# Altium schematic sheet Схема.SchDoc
size A0; SheetNumber: 0; SheetTotal: 0
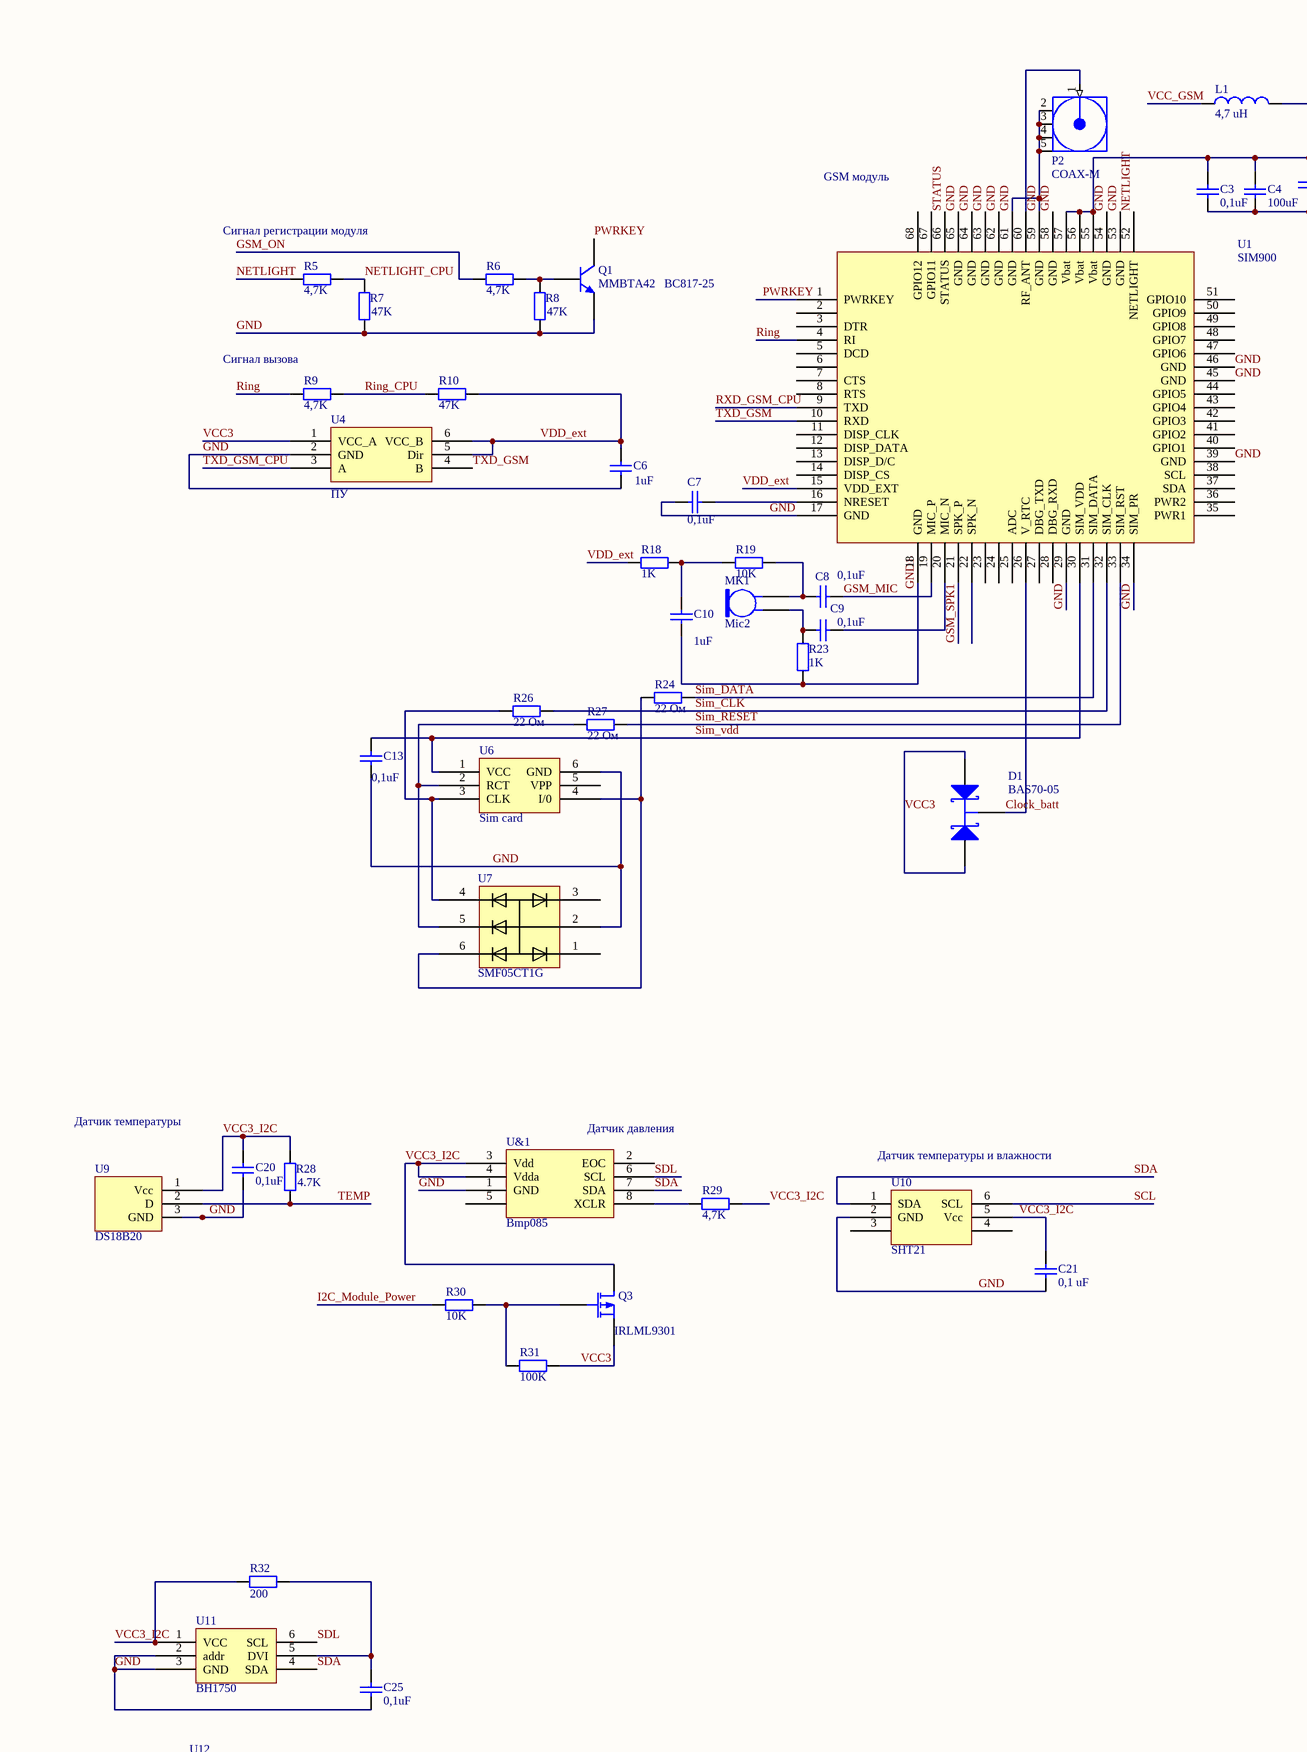
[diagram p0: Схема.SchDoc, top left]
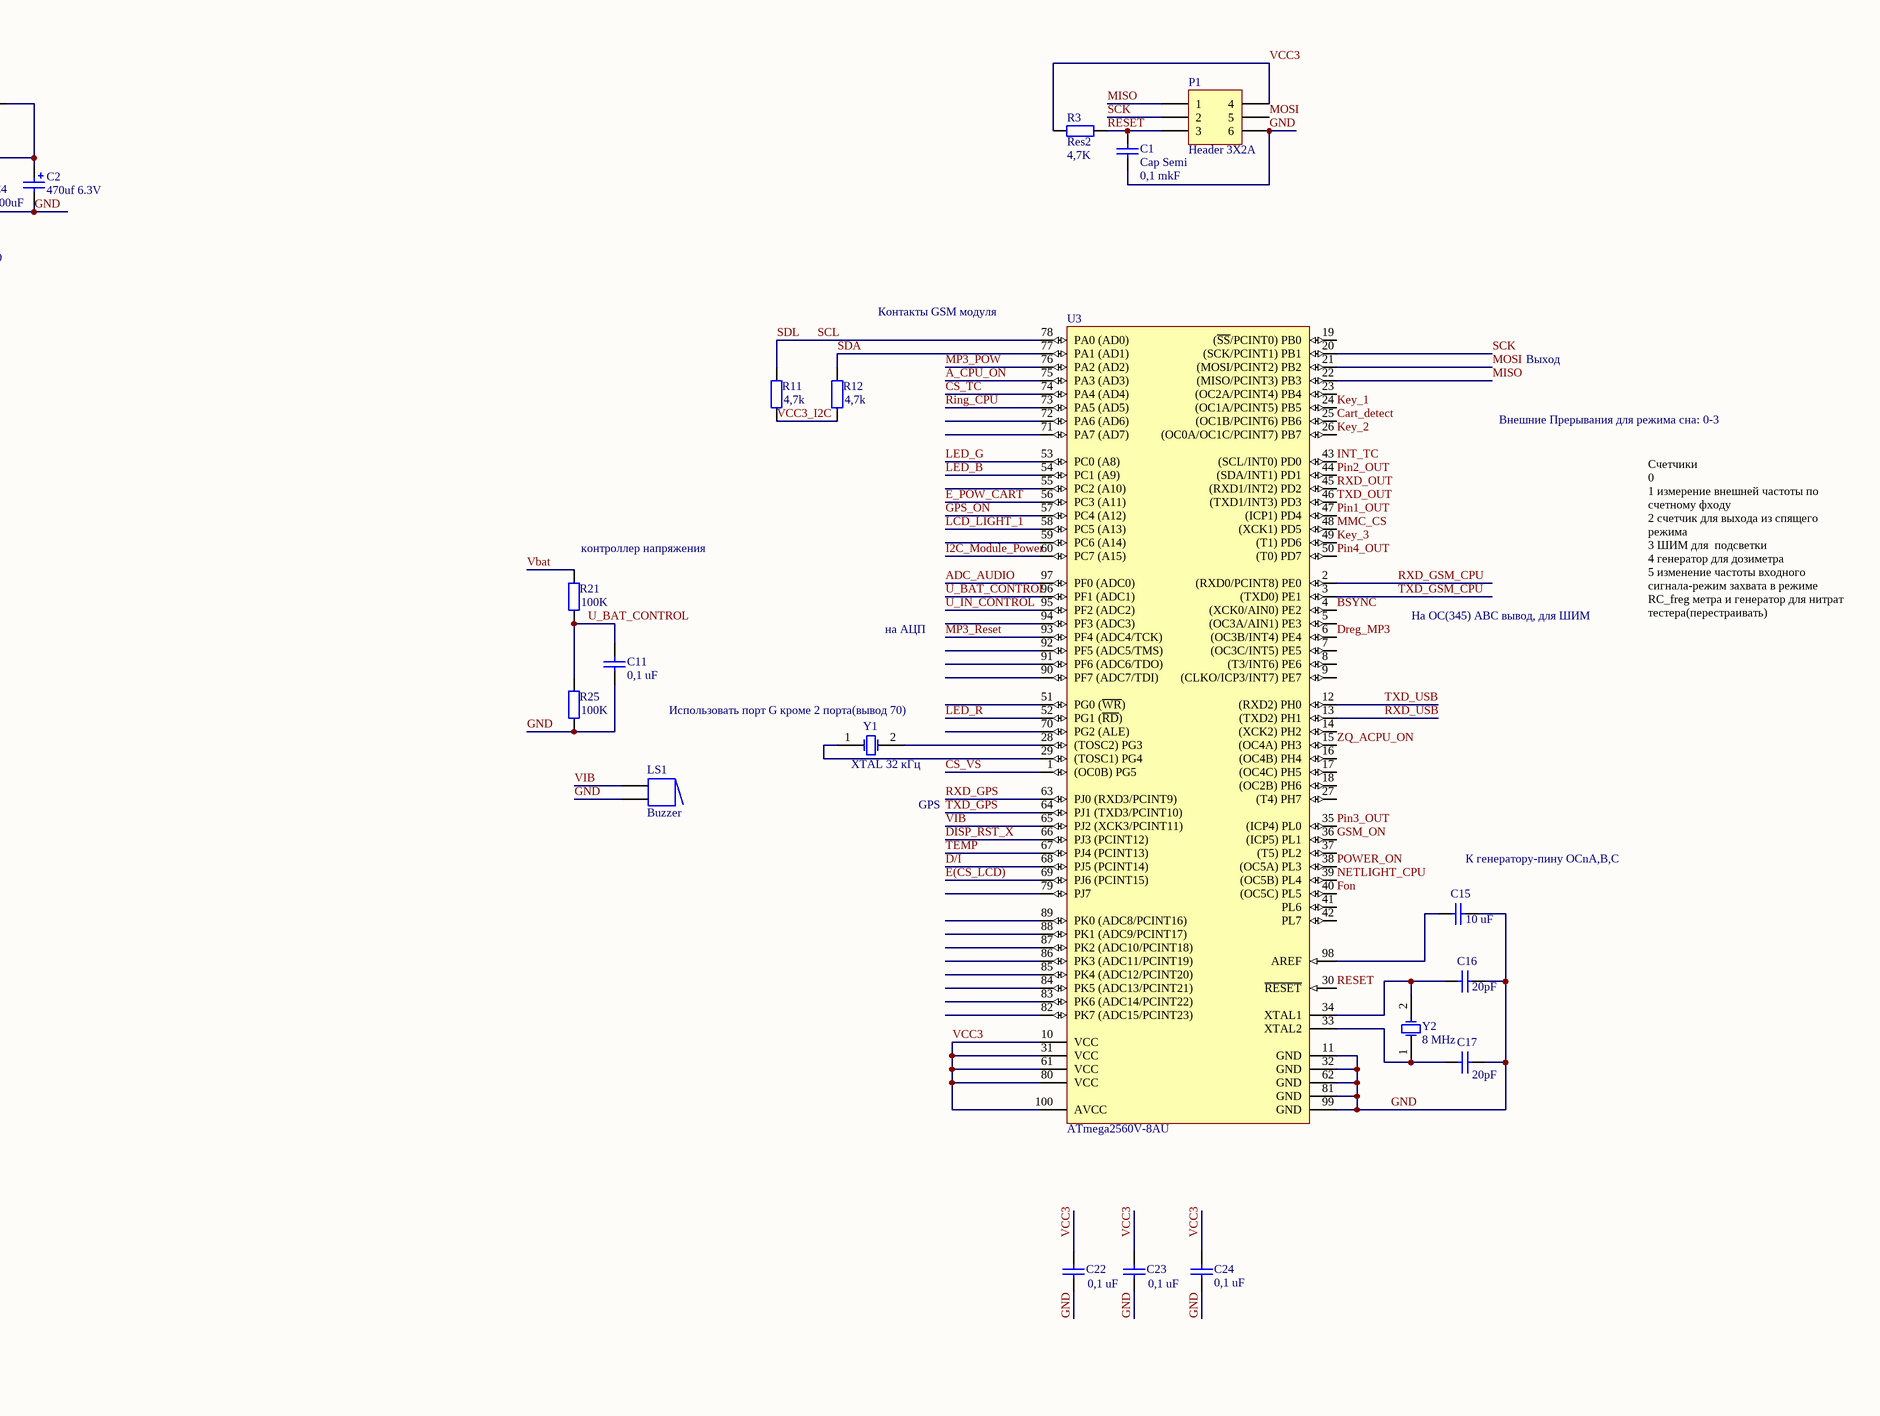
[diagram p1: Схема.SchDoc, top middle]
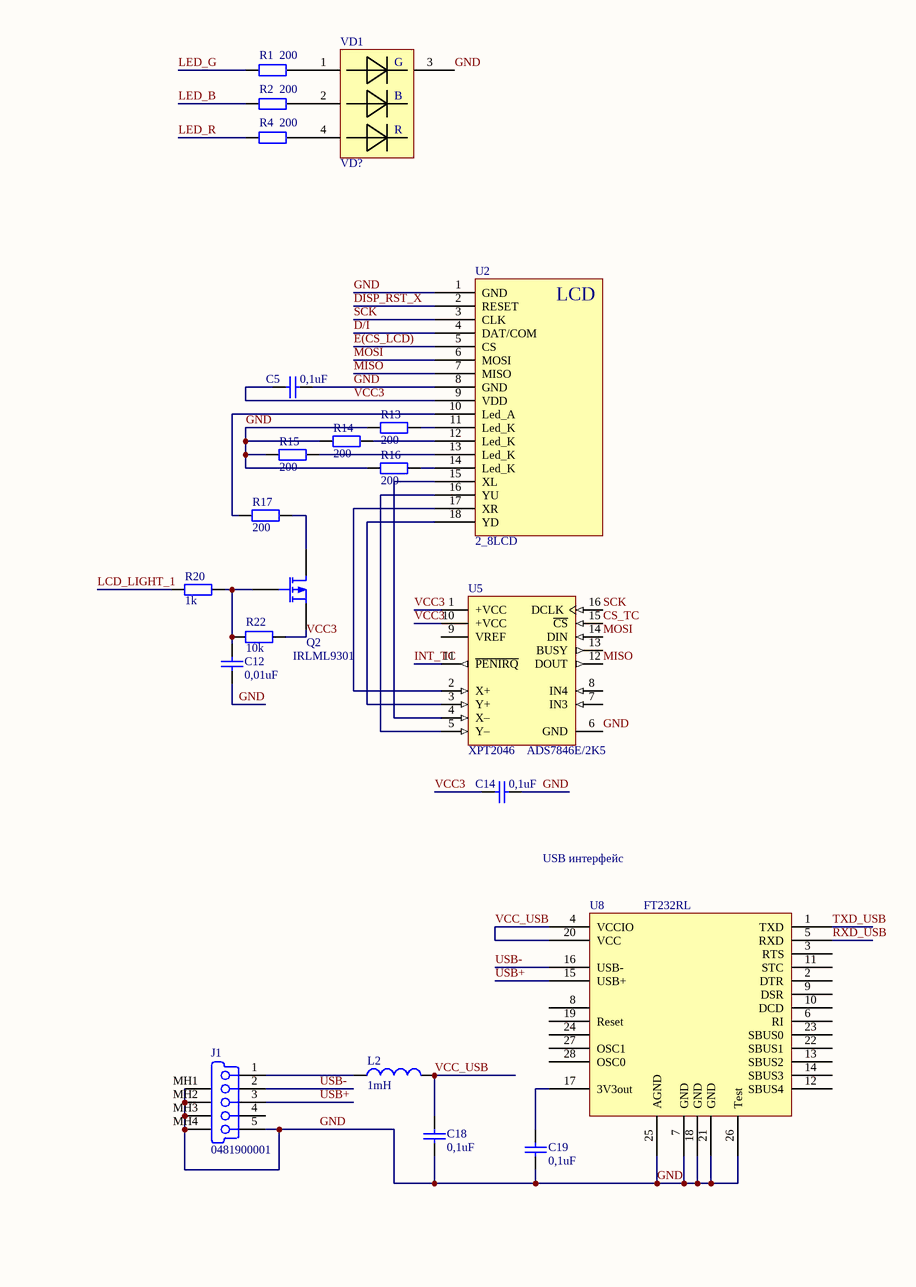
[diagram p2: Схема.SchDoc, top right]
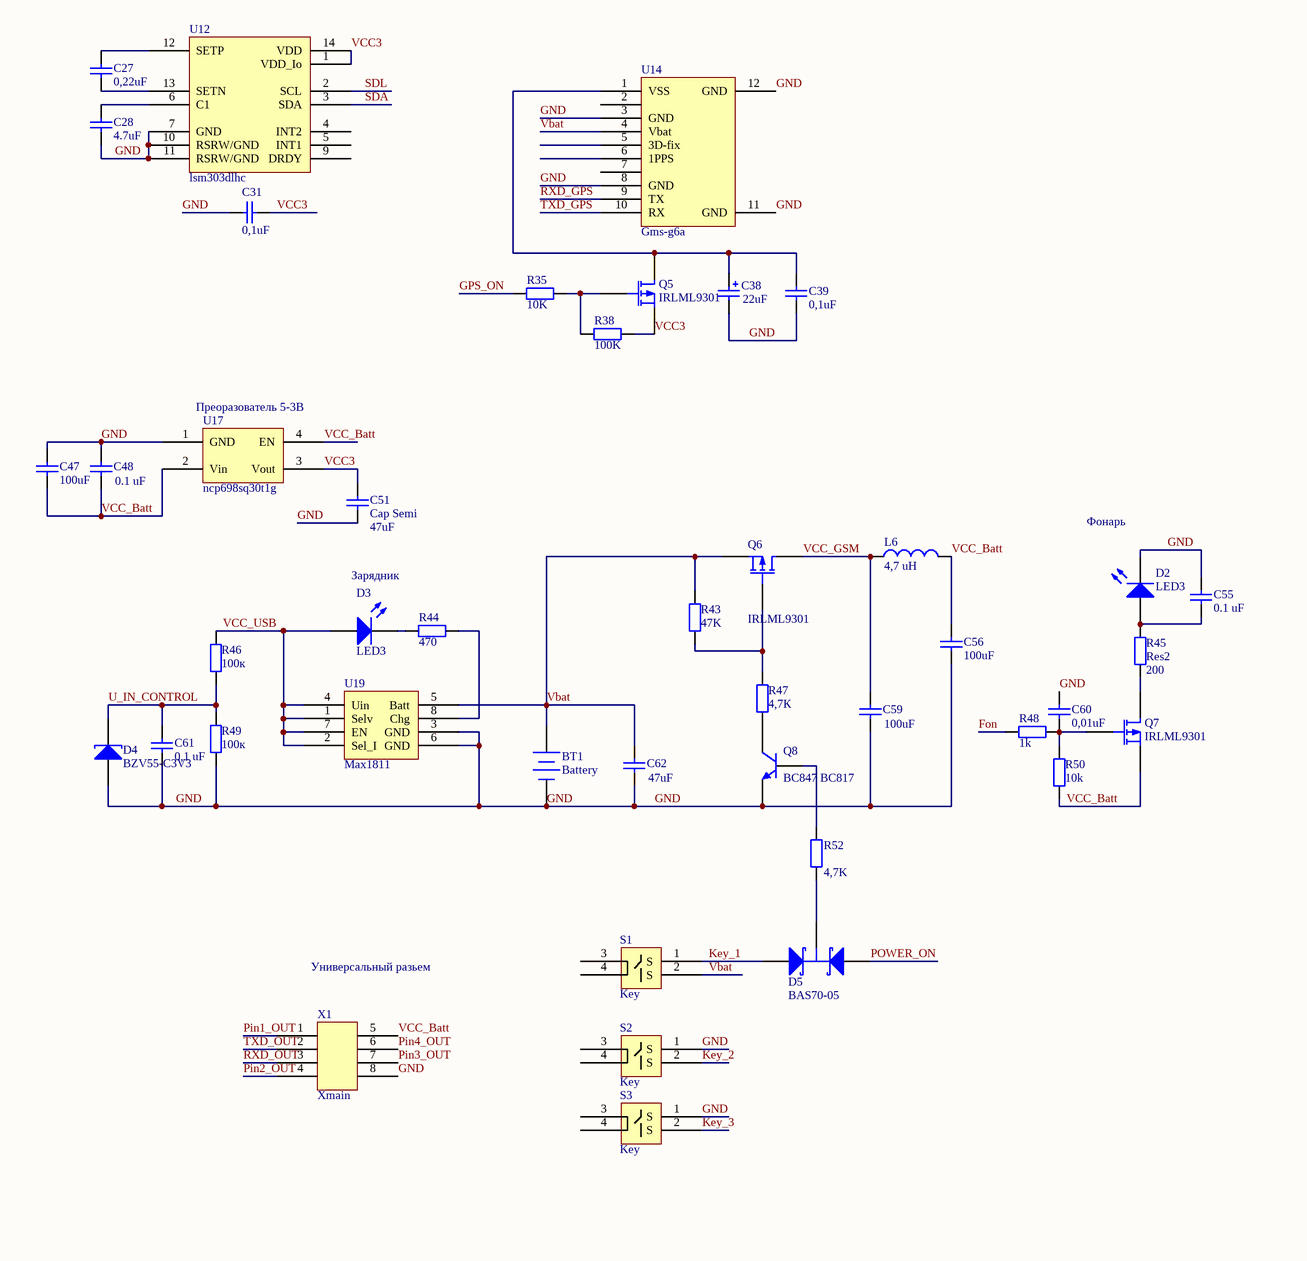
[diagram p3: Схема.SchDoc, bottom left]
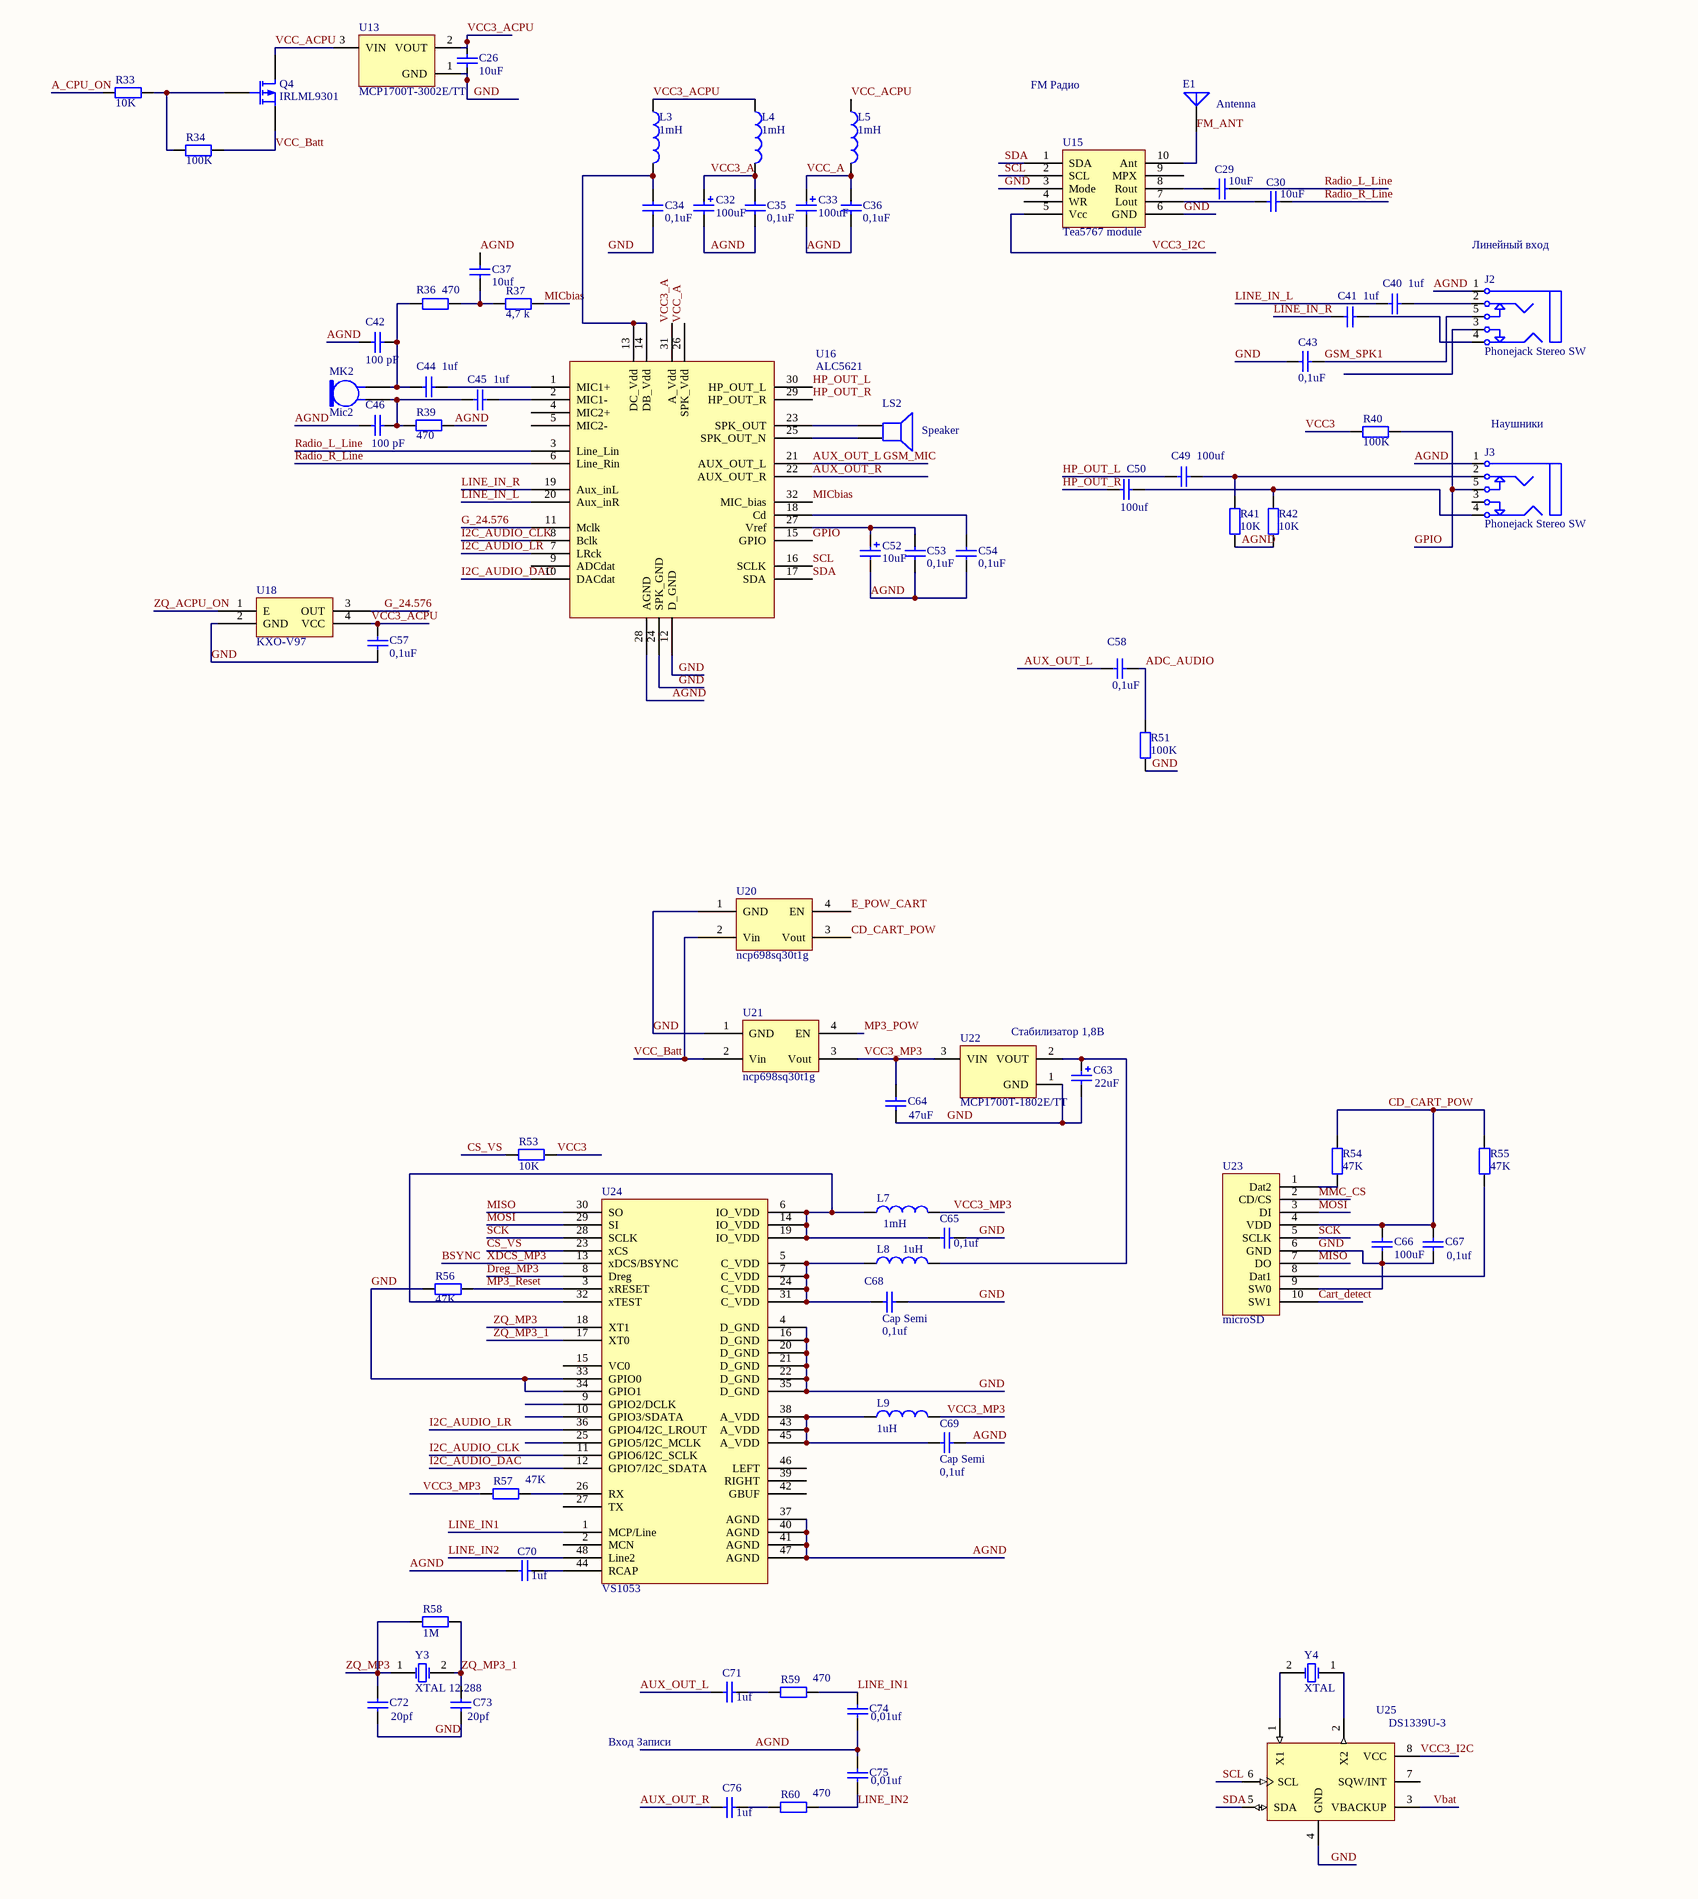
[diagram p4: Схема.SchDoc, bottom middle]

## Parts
BT1  Battery  [BAT-2]
C1  Cap Semi  value 0,1 mkF  [6-0805_L]
C2  value 470uf 6.3V  [HDR1X2]  (hidden comment: Cap Pol2)
C3  value 0,1uF  [C0805]  (hidden comment: Cap Semi)
C4  value 100uF  [C1206]  (hidden comment: Cap Semi)
C5  value 0,1uF  [C0805]  (hidden comment: Cap Semi)
C6  value 1uF  [C0805]  (hidden comment: Cap Semi)
C7  value 0,1uF  [C0805]  (hidden comment: Cap Semi)
C8  value 0,1uF  [C0805]  (hidden comment: Cap Semi)
C9  value 0,1uF  [C0805]  (hidden comment: Cap Semi)
C10  value 1uF  [C0805]  (hidden comment: Cap Semi)
C11  value 0,1 uF  [C0805]  (hidden comment: Cap Semi)
C12  value 0,01uF  [C0805]  (hidden comment: Cap Semi)
C13  value 0,1uF  [C0805]  (hidden comment: Cap Semi)
C14  value 0,1uF  [C0805]  (hidden comment: Cap Semi)
C15  value 10 uF  [C0805]  (hidden comment: Cap Semi)
C16  value 20pF  [C0805]  (hidden comment: Cap Semi)
C17  value 20pF  [C0805]  (hidden comment: Cap Semi)
C18  value 0,1uF  [C0805]  (hidden comment: Cap Semi)
C19  value 0,1uF  [C0805]  (hidden comment: Cap Semi)
C20  value 0,1uF  [C0805]  (hidden comment: Cap Semi)
C21  value 0,1 uF  [C0805]  (hidden comment: Cap Semi)
C22  value 0,1 uF  [C0805]  (hidden comment: Cap Semi)
C23  value 0,1 uF  [C0805]  (hidden comment: Cap Semi)
C24  value 0,1 uF  [C0805]  (hidden comment: Cap Semi)
C25  value 0,1uF  [C0805]  (hidden comment: Cap Semi)
C26  value 10uF  [C0805]  (hidden comment: Cap Semi)
C27  value 0,22uF  [C0805]  (hidden comment: Cap Semi)
C28  value 4.7uF  [C0805]  (hidden comment: Cap Semi)
C29  value 10uF  [C0805]  (hidden comment: Cap Semi)
C30  value 10uF  [C0805]  (hidden comment: Cap Semi)
C31  value 0,1uF  [C0805]  (hidden comment: Cap Semi)
C32  value 100uF  [C1206]  (hidden comment: Cap Pol2)
C33  value 100uF  [C1206]  (hidden comment: Cap Pol2)
C34  value 0,1uF  [C0805]  (hidden comment: Cap Semi)
C35  value 0,1uF  [C0805]  (hidden comment: Cap Semi)
C36  value 0,1uF  [C0805]  (hidden comment: Cap Semi)
C37  value 10uf  [C0805]  (hidden comment: Cap Semi)
C38  value 22uF  [C1206]  (hidden comment: Cap Pol2)
C39  value 0,1uF  [C0805]  (hidden comment: Cap Semi)
C40  value 1uf  [C0805]  (hidden comment: Cap Semi)
C41  value 1uf  [C0805]  (hidden comment: Cap Semi)
C42  value 100 pF  [C0805]  (hidden comment: Cap Semi)
C43  value 0,1uF  [C0805]  (hidden comment: Cap Semi)
C44  value 1uf  [C0805]  (hidden comment: Cap Semi)
C45  value 1uf  [C0805]  (hidden comment: Cap Semi)
C46  value 100 pF  [C0805]  (hidden comment: Cap Semi)
C47  value 100uF  [C1206]  (hidden comment: Cap Semi)
C48  value 0.1 uF  [C0805]  (hidden comment: Cap Semi)
C49  value 100uf  [C1206]  (hidden comment: Cap Semi)
C50  value 100uf  [C1206]  (hidden comment: Cap Semi)
C51  Cap Semi  value 47uF  [C1206]
C52  value 10uF  [C1206]  (hidden comment: Cap Pol2)
C53  value 0,1uF  [C0805]  (hidden comment: Cap Semi)
C54  value 0,1uF  [C0805]  (hidden comment: Cap Semi)
C55  value 0.1 uF  [C0805]  (hidden comment: Cap Semi)
C56  value 100uF  [C1206]  (hidden comment: Cap Semi)
C57  value 0,1uF  [C0805]  (hidden comment: Cap Semi)
C58  value 0,1uF  [C0805]  (hidden comment: Cap Semi)
C59  value 100uF  [C1206]  (hidden comment: Cap Semi)
C60  value 0,01uF  [C0805]  (hidden comment: Cap Semi)
C61  value 0,1 uF  [C0805]  (hidden comment: Cap Semi)
C62  value 47uF  [C1206]  (hidden comment: Cap Semi)
C63  value 22uF  [C0805]  (hidden comment: Cap Pol2)
C64  value 47uF  [C1206]  (hidden comment: Cap Semi)
C65  value 0,1uf  [C0805]  (hidden comment: Cap Semi)
C66  value 100uF  [C1206]  (hidden comment: Cap Semi)
C67  value 0,1uf  [C0805]  (hidden comment: Cap Semi)
C68  Cap Semi  value 0,1uf  [C0805]
C69  Cap Semi  value 0,1uf  [C0805]
C70  value 1uf  [C0805]  (hidden comment: Cap Semi)
C71  value 1uf  [C0805]  (hidden comment: Cap Semi)
C72  value 20pf  [C0805]  (hidden comment: Cap Semi)
C73  value 20pf  [C0805]  (hidden comment: Cap Semi)
C74  value 0,01uf  [C0805]  (hidden comment: Cap Semi)
C75  value 0,01uf  [C0805]  (hidden comment: Cap Semi)
C76  value 1uf  [C0805]  (hidden comment: Cap Semi)
D1  BAS70-05  [SOT-23]
D2  LED3  [BAT-2]
D3  LED3  [BAT-2]
D4  BZV55-C3V3  [3.2X1.6X1.1]
D5  BAS70-05  [SOT-23]
E1  Antenna  [PIN1]
J1  0481900001  [ATB3225]
J2  Phonejack Stereo SW  [AUDIO 3.5]
J3  Phonejack Stereo SW  [AUDIO 3.5]
L1  value 4,7 uH  [C1206]  (hidden comment: Inductor)
L2  value 1mH  [C0805]  (hidden comment: Inductor)
L3  value 1mH  [C1206]  (hidden comment: Inductor)
L4  value 1mH  [C1206]  (hidden comment: Inductor)
L5  value 1mH  [C1206]  (hidden comment: Inductor)
L6  value 4,7 uH  [C1206]  (hidden comment: Inductor)
L7  value 1mH  [C0805]  (hidden comment: Inductor)
L8  value 1uH  [C0805]  (hidden comment: Inductor)
L9  value 1uH  [C0805]  (hidden comment: Inductor)
LS1  Buzzer  [BAT-2]
LS2  Speaker  [PIN2]
MK1  Mic2  [PIN2]
MK2  Mic2  [PIN2]
P1  Header 3X2A  [HDR2X3_CEN]
P2  COAX-M  [sma]
Q1  MMBTA42   BC817-25  [SOT23_N]
Q2  IRLML9301  [VT]
Q3  IRLML9301  [VT]
Q4  IRLML9301  [VT]
Q5  IRLML9301  [VT]
Q6  IRLML9301  [VT]
Q7  IRLML9301  [VT]
Q8  BC847 BC817  [SOT23_N]
R1  value 200  [6-0805_L]  (hidden comment: Res2)
R2  value 200  [6-0805_L]  (hidden comment: Res2)
R3  Res2  value 4,7K  [6-0805_L]
R4  value 200  [6-0805_L]  (hidden comment: Res2)
R5  value 4,7K  [C0805]  (hidden comment: Res2)
R6  value 4,7K  [C0805]  (hidden comment: Res2)
R7  value 47K  [C0805]  (hidden comment: Res2)
R8  value 47K  [C0805]  (hidden comment: Res2)
R9  value 4,7K  [C0805]  (hidden comment: Res2)
R10  value 47K  [C0805]  (hidden comment: Res2)
R11  value 4,7k  [6-0805_L]  (hidden comment: Res2)
R12  value 4,7k  [6-0805_L]  (hidden comment: Res2)
R13  value 200  [6-0805_L]  (hidden comment: Res2)
R14  value 200  [6-0805_L]  (hidden comment: Res2)
R15  value 200  [6-0805_L]  (hidden comment: Res2)
R16  value 200  [6-0805_L]  (hidden comment: Res2)
R17  value 200  [6-0805_L]  (hidden comment: Res2)
R18  value 1K  [C0805]  (hidden comment: Res2)
R19  value 10K  [C0805]  (hidden comment: Res2)
R20  value 1k  [6-0805_L]  (hidden comment: Res2)
R21  value 100K  [C0805]  (hidden comment: Res2)
R22  value 10k  [6-0805_L]  (hidden comment: Res2)
R23  value 1K  [C0805]  (hidden comment: Res2)
R24  value 22 Ом  [C0805]  (hidden comment: Res2)
R25  value 100K  [6-0805_L]  (hidden comment: Res2)
R26  value 22 Ом  [C0805]  (hidden comment: Res2)
R27  value 22 Ом  [C0805]  (hidden comment: Res2)
R28  value 4.7K  [6-0805_L]  (hidden comment: Res2)
R29  value 4,7K  [6-0805_L]  (hidden comment: Res2)
R30  value 10K  [6-0805_N]  (hidden comment: Res2)
R31  value 100K  [6-0805_N]  (hidden comment: Res2)
R32  value 200  [6-0805_L]  (hidden comment: Res2)
R33  value 10K  [6-0805_N]  (hidden comment: Res2)
R34  value 100K  [6-0805_N]  (hidden comment: Res2)
R35  value 10K  [6-0805_N]  (hidden comment: Res2)
R36  value 470  [C0805]  (hidden comment: Res2)
R37  value 4,7 k  [C0805]  (hidden comment: Res2)
R38  value 100K  [6-0805_N]  (hidden comment: Res2)
R39  value 470  [C0805]  (hidden comment: Res2)
R40  value 100K  [6-0805_N]  (hidden comment: Res2)
R41  value 10K  [6-0805_N]  (hidden comment: Res2)
R42  value 10K  [6-0805_N]  (hidden comment: Res2)
R43  value 47K  [6-0805_N]  (hidden comment: Res2)
R44  value 470  [6-0805_L]  (hidden comment: Res2)
R45  Res2  value 200  [6-0805_L]
R46  value 100к  [6-0805_L]  (hidden comment: Res2)
R47  value 4,7К  [6-0805_N]  (hidden comment: Res2)
R48  value 1k  [6-0805_L]  (hidden comment: Res2)
R49  value 100к  [6-0805_L]  (hidden comment: Res2)
R50  value 10k  [6-0805_L]  (hidden comment: Res2)
R51  value 100K  [C0805]  (hidden comment: Res2)
R52  value 4,7K  [6-0805_L]  (hidden comment: Res2)
R53  value 10K  [C0805]  (hidden comment: Res2)
R54  value 47K  [C0805]  (hidden comment: Res2)
R55  value 47K  [C0805]  (hidden comment: Res2)
R56  value 47K  [C0805]  (hidden comment: Res2)
R57  value 47K  [C0805]  (hidden comment: Res2)
R58  value 1M  [C0805]  (hidden comment: Res2)
R59  value 470  [C0805]  (hidden comment: Res2)
R60  value 470  [C0805]  (hidden comment: Res2)
S1  Key  [Key]
S2  Key  [Key]
S3  Key  [Key]
U1  SIM900  [SIM900_]
U2  2_8LCD  [LCD 2.8]
U3  ATmega2560V-8AU  [100]
U4  ПУ  [Преобразователь уровней SN74LVC1T45]
U5  XPT2046    ADS7846E/2K5  [TC]
U6  Sim card  [SIM-06]
U7  SMF05CT1G  [SMF05CT1G]
U8  FT232RL  [FT232RL]
U9  DS18B20  [DS18B20]
U10  SHT21  [Датчик]
U11  BH1750  [BH1750]
U12  lsm303dlhc  [lsm303dlhc]
U13  MCP1700T-3002E/TT  [VT]
U14  Gms-g6a  [GPS Gms-g6a]
U15  Tea5767 module  [FM AR1310]
U16  ALC5621  [AUDIO CODEC]
U17  ncp698sq30t1g  [St_3V0]
U18  KXO-V97  [25]
U19  Max1811  [SOIC8N_N]
U20  ncp698sq30t1g  [St_3V0_ver2]
U21  ncp698sq30t1g  [St_3V0]
U22  MCP1700T-1802E/TT  [VT]
U23  microSD  [microSD_PCB]
U24  VS1053  [DIP8]
U25  DS1339U-3  [8uSOP]
U&1  Bmp085  [Датчик давления Bmp085]
VD1  VD?  [RGB_5mm_Led]
X1  Xmain  [Xmain]
Y1  XTAL 32 кГц  [R38]
Y2  8 MHz  [HC-49U]
Y3  XTAL 12.288  [ZQ]
Y4  XTAL  [32768]

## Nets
A_CPU_ON: R33.2 U3.75(PA3_(AD3))
ADC_AUDIO: C58.2 R51.1 U3.97(PF0_(ADC0))
AGND: C32.2 C33.2 C35.2 C36.2 C37.2 C42.1 C46.1 C52.2 C53.2 C54.2 C69.1 C70.2 C74.2 C75.1 J2.1 J3.1 R39.1 R41.2 R42.2 U16.28(AGND) U24.37(AGND) U24.40(AGND) U24.41(AGND) U24.47(AGND)
AUX_OUT_L: C8.2 C58.1 C71.2 U1.19(MIC_P) U16.21(AUX_OUT_L)  [also labelled GSM_MIC]
AUX_OUT_R: C76.2 U16.22(AUX_OUT_R)
BSYNC: U3.4((XCK0/AIN0)_PE2) U24.13(xDCS/BSYNC)  [also labelled XDCS_MP3]
Cart_detect: U3.25((OC1B/PCINT6)_PB6) U23.10(SW1)
CD_CART_POW: C66.2 C67.1 R54.1 R55.1 U20.3(Vout) U23.4(VDD)
Clock_batt: D1.3(K) U1.26(V_RTC)
CS_TC: U3.74(PA4_(AD4)) U5.15(~{CS})
CS_VS: R53.2 U3.1((OC0B)_PG5) U24.23(xCS)
D/I: U2.4(DAT/COM) U3.68(PJ5_(PCINT14))
DISP_RST_X: U2.2(RESET) U3.66(PJ3_(PCINT12))
Dreg_MP3: U3.6((OC3B/INT4)_PE4) U24.8(Dreg)
E(CS_LCD): U2.5(CS) U3.69(PJ6_(PCINT15))
E_POW_CART: U3.56(PC3_(A11)) U20.4(EN)
FM_ANT: E1.1(A) U15.10(Ant)
Fon: R48.1 U3.40((OC5C)_PL5)
G_24.576: U16.11(Mclk) U18.3(OUT)
GND: BT1.2(-) C1.1 C2.2 C3.2 C4.2 C5.2 C6.1 C7.1 C11.1 C12.2 C13.1 C14.2 C15.1 C16.2 C17.2 C18.1 C19.1 C20.2 C21.1 C22.1 C23.1 C24.1 C25.2 C26.1 C28.1 C31.2 C34.2 C38.2 C39.2 C43.1 C47.1 C48.2 C51.1 C55.1 C56.2 C57.2 C59.2 C60.1 C61.2 C62.2 C63.2 C64.2 C65.1 C66.1 C67.2 C68.1 C72.2 C73.2 D2.2(K) D4.1(A) J1.5(GND) J1.MH1(Tab) J1.MH2(Tab) J1.MH3(Tab) J1.MH4(Tab) LS1.2 P1.6 P2.2(GND) P2.3(GND) P2.4(GND) P2.5(GND) Q1.2(E) Q8.2(E) R7.2 R8.2 R13.1 R14.1 R15.1 R16.1 R25.2 R49.1 R51.2 R56.1 S2.1(S) S3.1(S) U1.17(GND) U1.29(GND) U1.34(SIM_PR) U1.39(GND) U1.45(GND) U1.46(GND) U1.53(GND) U1.54(GND) U1.58(GND) U1.59(GND) U1.61(GND) U1.62(GND) U1.63(GND) U1.64(GND) U1.65(GND) U2.1(GND) U2.8(GND) U3.11(GND) U3.32(GND) U3.62(GND) U3.81(GND) U3.99(GND) U4.2(GND) U5.6(GND) U6.6(GND) U7.2 U8.7(GND) U8.18(GND) U8.21(GND) U8.25(AGND) U8.26(Test) U9.3(GND) U10.2(GND) U11.2(addr) U11.3(GND) U12.7(GND) U12.10(RSRW/GND) U12.11(RSRW/GND) U13.1(GND) U14.3(GND) U14.8(GND) U14.11(GND) U14.12(GND) U15.3(Mode) U15.6(GND) U16.12(D_GND) U16.24(SPK_GND) U17.1(GND) U18.2(GND) U19.3(GND) U19.6(GND) U20.1(GND) U21.1(GND) U22.1(GND) U23.6(GND) U23.9(SW0) U24.4(D_GND) U24.16(D_GND) U24.20(D_GND) U24.21(D_GND) U24.22(D_GND) U24.33(GPIO0) U24.34(GPIO1) U24.35(D_GND) U25.4(GND) U&1.1(GND) VD1.3 X1.8
GND1: C10.1 R23.1 U1.18(GND)
GPIO: J3.5 R40.2 U16.15(GPIO)
GPS_ON: R35.2 U3.57(PC4_(A12))
GSM_ON: R6.1 U3.36((ICP5)_PL1)
GSM_SPK1: C43.2 J2.5 U1.21(SPK_P)
HP_OUT_L: C49.1 U16.30(HP_OUT_L)
HP_OUT_R: C50.1 U16.29(HP_OUT_R)
I2C_AUDIO_CLK: U16.8(Bclk) U24.11(GPIO6/I2C_SCLK)
I2C_AUDIO_DAC: U16.10(DACdat) U24.12(GPIO7/I2C_SDATA)
I2C_AUDIO_LR: U16.7(LRck) U24.36(GPIO4/I2C_LROUT)
I2C_Module_Power: R30.2 U3.60(PC7_(A15))
INT_TC: U3.43((SCL/INT0)_PD0) U5.11(~{PENIRQ})
Key_1: D5.2(A2) S1.1(S) U3.24((OC1A/PCINT5)_PB5)
Key_2: S2.2(S) U3.26((OC0A/OC1C/PCINT7)_PB7)
Key_3: S3.2(S) U3.49((T1)_PD6)
LCD_LIGHT_1: R20.1 U3.58(PC5_(A13))
LED_B: R2.1 U3.54(PC1_(A9))
LED_G: R1.1 U3.53(PC0_(A8))
LED_R: R4.1 U3.52(PG1_(~{RD}))
LINE_IN1: C74.1 R59.2 U24.1(MCP/Line)
LINE_IN2: C75.2 R60.2 U24.48(Line2)
LINE_IN_L: C40.1 U16.20(Aux_inR)
LINE_IN_R: C41.1 U16.19(Aux_inL)
MICbias: R37.1 U16.32(MIC_bias)
MISO: P1.1 U2.7(MISO) U3.22((MISO/PCINT3)_PB3) U5.12(DOUT) U23.7(DO) U24.30(SO)
MMC_CS: U3.48((XCK1)_PD5) U23.2(CD/CS)
MOSI: P1.5 U2.6(MOSI) U3.21((MOSI/PCINT2)_PB2) U5.14(DIN) U23.3(DI) U24.29(SI)
MP3_POW: U3.76(PA2_(AD2)) U21.4(EN)
MP3_Reset: R56.2 U3.93(PF4_(ADC4/TCK)) U24.3(xRESET)
NETLIGHT: R5.1 U1.52(NETLIGHT)
NETLIGHT_CPU: R5.2 R7.1 U3.39((OC5B)_PL4)
Pin1_OUT: U3.47((ICP1)_PD4) X1.1
Pin2_OUT: U3.44((SDA/INT1)_PD1) X1.4
Pin3_OUT: U3.35((ICP4)_PL0) X1.7
Pin4_OUT: U3.50((T0)_PD7) X1.6
POWER_ON: D5.1(A1) U3.38((OC5A)_PL3)
PWRKEY: Q1.3(C) U1.1(PWRKEY)
Radio_L_Line: C29.2 U16.3(Line_Lin)
Radio_R_Line: C30.2 U16.6(Line_Rin)
RESET: C1.2 P1.3 R3.1 U3.30(~{RESET})
Ring: R9.1 U1.4(RI)
Ring_CPU: R9.2 R10.1 U3.73(PA5_(AD5))
RXD_GPS: U3.63(PJ0_(RXD3/PCINT9)) U14.9(TX)
RXD_GSM_CPU: U1.9(TXD) U3.2((RXD0/PCINT8)_PE0)
RXD_OUT: U3.45((RXD1/INT2)_PD2) X1.3
RXD_USB: U3.13((TXD2)_PH1) U8.5(RXD)
SCK: P1.2 U2.3(CLK) U3.20((SCK/PCINT1)_PB1) U5.16(DCLK) U23.5(SCLK) U24.28(SCLK)
SCL: R11.1 U3.78(PA0_(AD0)) U10.6(SCL) U11.6(SCL) U12.2(SCL) U15.2(SCL) U16.16(SCLK) U25.6(SCL) U&1.6(SCL)  [also labelled SDL]
SDA: R12.1 U3.77(PA1_(AD1)) U10.1(SDA) U11.4(SDA) U12.3(SDA) U15.1(SDA) U16.17(SDA) U25.5(SDA) U&1.7(SDA)
Sim_CLK: R26.2 U1.32(SIM_CLK)
Sim_DATA: R24.2 U1.31(SIM_DATA)
Sim_RESET: R27.2 U1.33(SIM_RST)
Sim_vdd: C13.2 U1.30(SIM_VDD) U6.1(VCC)
STATUS: U1.66(STATUS)
TEMP: R28.2 U3.67(PJ4_(PCINT13)) U9.2(D)
TXD_GPS: U3.64(PJ1_(TXD3/PCINT10)) U14.10(RX)
TXD_GSM: U1.10(RXD) U4.4(B)
TXD_GSM_CPU: U3.3((TXD0)_PE1) U4.3(A)
TXD_OUT: U3.46((TXD1/INT3)_PD3) X1.2
TXD_USB: U3.12((RXD2)_PH0) U8.1(TXD)
U_BAT_CONTROL: C11.2 R21.2 R25.1 U3.96(PF1_(ADC1))
U_IN_CONTROL: C61.1 D4.2(K) R46.1 R49.2 U3.95(PF2_(ADC2))
USB+: J1.3(D+) U8.15(USB+)
USB-: J1.2(D-) U8.16(USB-)
Vbat: BT1.1(+) C62.1 Q6.2(S) R21.1 R43.1 S1.2(S) U14.4(Vbat) U19.5(Batt) U25.3(VBACKUP)
VCC3: C5.1 C14.1 C22.2 C23.2 C24.2 C31.1 C51.2 D1.1(A1) D1.2(A2) P1.4 Q2.2(S) Q3.2(S) Q5.2(S) R3.2 R22.2 R31.1 R38.1 R40.1 R53.1 U2.9(VDD) U3.10(VCC) U3.31(VCC) U3.61(VCC) U3.80(VCC) U3.100(AVCC) U4.1(VCC_A) U5.1(+VCC) U5.10(+VCC) U12.1(VDD_Io) U12.14(VDD) U17.3(Vout)
VCC3_A: C32.1 C35.1 L4.2 U16.31(A_Vdd)
VCC3_ACPU: C26.2 C57.1 L3.1 L4.1 U13.2(VOUT) U18.4(VCC)
VCC3_I2C: C20.1 C21.2 Q3.3(D) R11.2 R12.2 R28.1 R29.2 R32.2 U9.1(Vcc) U10.5(Vcc) U11.1(VCC) U15.5(Vcc) U25.8(VCC) U&1.3(Vdd) U&1.4(Vdda)
VCC3_MP3: C64.1 L7.2 L9.2 R57.1 U21.3(Vout) U22.3(VIN)
VCC_A: C33.1 C36.1 L5.2 U16.26(SPK_Vdd)
VCC_ACPU: L5.1 Q4.3(D) U13.3(VIN)
VCC_Batt: C47.2 C48.1 C56.1 L6.2 Q4.2(S) Q7.2(S) R34.1 R50.1 U17.2(Vin) U17.4(EN) U20.2(Vin) U21.2(Vin) X1.5
VCC_GSM: C59.1 L1.1 L6.1 Q6.3(D)
VCC_USB: C18.2 D3.1(A) L2.2 R46.2 U8.4(VCCIO) U8.20(VCC) U19.1(Selv) U19.2(Sel_I) U19.4(Uin) U19.7(EN)
VDD_ext: C6.2 R10.2 R18.2 U1.15(VDD_EXT) U4.5(Dir) U4.6(VCC_B)
VIB: LS1.1 U3.65(PJ2_(XCK3/PCINT11))
ZQ_ACPU_ON: U3.15((OC4A)_PH3) U18.1(E)
ZQ_MP3: C72.1 R58.1 U24.18(XT1) Y3.1(OSC1)
ZQ_MP3_1: C73.1 R58.2 U24.17(XT0) Y3.2(OSC2)
NetC2_1: C2.1 C3.1 C4.1 L1.2 U1.55(Vbat) U1.56(Vbat) U1.57(Vbat)
NetC7_2: C7.2 U1.16(NRESET)
NetC8_1: C8.1 MK1.2 R19.1
NetC9_1: C9.1 MK1.1 R23.2
NetC9_2: C9.2 U1.20(MIC_N)
NetC10_2: C10.2 R18.1 R19.2
NetC12_1: C12.1 Q2.1(G) R20.2 R22.1
NetC15_2: C15.2 U3.98(AREF)
NetC16_1: C16.1 U3.34(XTAL1) Y2.2(OSC2)
NetC17_1: C17.1 U3.33(XTAL2) Y2.1(OSC1)
NetC19_2: C19.2 U8.17(3V3out)
NetC25_1: C25.1 R32.1 U11.5(DVI)
NetC27_1: C27.1 U12.13(SETN)
NetC27_2: C27.2 U12.12(SETP)
NetC28_2: C28.2 U12.6(C1)
NetC29_1: C29.1 U15.8(Rout)
NetC30_1: C30.1 U15.7(Lout)
NetC34_1: C34.1 L3.2 U16.13(DC_Vdd) U16.14(DB_Vdd)
NetC37_1: C37.1 R36.2 R37.2
NetC38_1: C38.1 C39.1 Q5.3(D) U14.1(VSS)
NetC40_2: C40.2 J2.2
NetC41_2: C41.2 J2.4
NetC42_2: C42.2 C44.1 MK2.2 R36.1
NetC44_2: C44.2 U16.1(MIC1+)
NetC45_1: C45.1 C46.2 MK2.1 R39.2
NetC45_2: C45.2 U16.2(MIC1-)
NetC49_2: C49.2 J3.2 R41.1
NetC50_2: C50.2 J3.4 R42.1
NetC52_1: C52.1 C53.1 U16.27(Vref)
NetC54_1: C54.1 U16.18(Cd)
NetC55_2: C55.2 D2.1(A) R45.2
NetC60_2: C60.2 Q7.1(G) R48.2 R50.2
NetC63_1: C63.1 L8.2 U22.2(VOUT)
NetC65_2: C65.2 L7.1 U24.6(IO_VDD) U24.14(IO_VDD) U24.19(IO_VDD) U24.32(xTEST)
NetC68_2: C68.2 L8.1 U24.5(C_VDD) U24.7(C_VDD) U24.24(C_VDD) U24.31(C_VDD)
NetC69_2: C69.2 L9.1 U24.38(A_VDD) U24.43(A_VDD) U24.45(A_VDD)
NetC70_1: C70.1 U24.44(RCAP)
NetC71_1: C71.1 R59.1
NetC76_1: C76.1 R60.1
NetD3_2: D3.2(K) R44.1
NetD5_3: D5.3(K) R52.2
NetJ1_1: J1.1(V_BUS_(5V)) L2.1
NetLS2_1: LS2.1 U16.23(SPK_OUT)
NetLS2_2: LS2.2 U16.25(SPK_OUT_N)
NetP2_1: P2.1(Signal) U1.60(RF_ANT)
NetQ1_1: Q1.1(B) R6.2 R8.1
NetQ2_3: Q2.3(D) R17.2
NetQ3_1: Q3.1(G) R30.1 R31.2
NetQ4_1: Q4.1(G) R33.1 R34.2
NetQ5_1: Q5.1(G) R35.1 R38.2
NetQ6_1: Q6.1(G) R43.2 R47.1
NetQ7_3: Q7.3(D) R45.1
NetQ8_1: Q8.1(B) R52.1
NetQ8_3: Q8.3(C) R47.2
NetR1_2: R1.2 VD1.1
NetR2_2: R2.2 VD1.2
NetR4_2: R4.2 VD1.4
NetR13_2: R13.2 U2.11(Led_K)
NetR14_2: R14.2 U2.12(Led_K)
NetR15_2: R15.2 U2.13(Led_K)
NetR16_2: R16.2 U2.14(Led_K)
NetR17_1: R17.1 U2.10(Led_A)
NetR24_1: R24.1 U6.4(I/0) U7.6
NetR26_1: R26.1 U6.3(CLK) U7.4
NetR27_1: R27.1 U6.2(RCT) U7.5
NetR29_1: R29.1 U&1.8(XCLR)
NetR44_2: R44.2 U19.8(Chg)
NetR54_2: R54.2 U23.1(Dat2)
NetR55_2: R55.2 U23.8(Dat1)
NetR57_2: R57.2 U24.26(RX)
NetU2_15: U2.15(XL) U5.4(X–)
NetU2_16: U2.16(YU) U5.5(Y–)
NetU2_17: U2.17(XR) U5.2(X+)
NetU2_18: U2.18(YD) U5.3(Y+)
NetU3_28: U3.28((TOSC2)_PG3) Y1.2(OSC2)
NetU3_29: U3.29((TOSC1)_PG4) Y1.1(OSC1)
NetU25_1: U25.1(X1) Y4.2(OSC2)
NetU25_2: U25.2(X2) Y4.1(OSC1)

Not connected (* = marked no-connect by the designer): J1 4(NC); J2 3; J3 3; S1 3 4; S2 3 4; S3 3 4; U1 2 3(DTR) 5(DCD) 6 7(CTS) 8(RTS) 11(DISP_CLK) 12(DISP_DATA) 13(DISP_D/C) 14(DISP_CS) 22(SPK_N) 23 24 25(ADC) 27(DBG_TXD) 28(DBG_RXD) 35(PWR1) 36(PWR2) 37(SDA) 38(SCL) 40(GPIO1) 41(GPIO2) 42(GPIO3) 43(GPIO4) 44(GPIO5) 47(GPIO6) 48(GPIO7) 49(GPIO8) 50(GPIO9) 51(GPIO10) 67(GPIO11) 68(GPIO12); U3 5((OC3A/AIN1)_PE3) 7((OC3C/INT5)_PE5) 8((T3/INT6)_PE6) 9((CLKO/ICP3/INT7)_PE7) 14((XCK2)_PH2) 16((OC4B)_PH4) 17((OC4C)_PH5) 18((OC2B)_PH6) 19((~{SS}/PCINT0)_PB0) 23((OC2A/PCINT4)_PB4) 27((T4)_PH7) 37((T5)_PL2) 41(PL6) 42(PL7) 51(PG0_(~{WR})) 55(PC2_(A10)) 59(PC6_(A14)) 70(PG2_(ALE)) 71(PA7_(AD7)) 72(PA6_(AD6)) 79(PJ7) 82(PK7_(ADC15/PCINT23)) 83(PK6_(ADC14/PCINT22)) 84(PK5_(ADC13/PCINT21)) 85(PK4_(ADC12/PCINT20)) 86(PK3_(ADC11/PCINT19)) 87(PK2_(ADC10/PCINT18)) 88(PK1_(ADC9/PCINT17)) 89(PK0_(ADC8/PCINT16)) 90(PF7_(ADC7/TDI)) 91(PF6_(ADC6/TDO)) 92(PF5_(ADC5/TMS)) 94(PF3_(ADC3)); U5 7(IN3) 8(IN4) 9(VREF) 13(BUSY); U6 5(VPP); U7 1 3; U8 2(DTR) 3(RTS) 6(RI) 8 9(DSR) 10(DCD) 11(STC) 12(SBUS4) 13(SBUS2) 14(SBUS3) 19(Reset) 22(SBUS1) 23(SBUS0) 24 27(OSC1) 28(OSC0); U10 3 4; U12 4(INT2) 5(INT1) 9(DRDY); U14 2 5(3D-fix) 6(1PPS) 7; U15 4(WR) 9(MPX); U16 4(MIC2+) 5(MIC2-) 9(ADCdat); U24 2(MCN) 9(GPIO2/DCLK) 10(GPIO3/SDATA) 15(VC0) 25(GPIO5/I2C_MCLK) 27(TX) 39(RIGHT) 42(GBUF) 46(LEFT); U25 7(SQW/INT); U&1 2(EOC) 5

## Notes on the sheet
- GSM модуль
- Сигнал регистрации модуля
- Контакты GSM модуля
- (near R9) Сигнал вызова
- Выход
- Внешние Прерывания для режима сна: 0-3
- (near R21) контроллер напряжения
- на АЦП
- На OC(345) ABC вывод, для ШИМ
- Счетчики
  0
  1 измерение внешней частоты по счетному фходу
  2 счетчик для выхода из спящего режима
  3 ШИМ для  подсветки
  4 генератор для дозиметра
  5 изменение частоты входного сигнала-режим захвата в режиме RC_freg метра и генератор для нитрат тестера(перестраивать)
- (near Y1) Использовать порт G кроме 2 порта(вывод 70)
- GPS
- (near C15) К генератору-пину OCnA,B,C
- USB интерфейс
- Датчик температуры
- (near U&1) Датчик давления
- (near U10) Датчик температуры и влажности
- FM Радио
- (near J2) Линейный вход
- (near U17) Преоразователь 5-3В
- (near J3) Наушники
- Фонарь
- Зарядник
- Универсальный разьем
- Стабилизатор 1,8В
- Вход Записи

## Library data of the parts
BT1 = Battery: Multicell Battery
C1 C3-C31 C34-C37 C39-C51 C53-C62 C64-C76 = Cap Semi: Capacitor (Semiconductor SIM Model)
C2 C32 C33 C38 C52 C63 = Cap Pol2: Polarized Capacitor (Axial)
D1 D5 = BAS70-05: Silicon AF Schottky Diode for High-Speed Switching
D2 D3 = LED3: Typical BLUE SiC LED
D4 = D Tunnel1: Tunnel Diode - RLC Model
E1 = Antenna: Generic Antenna
J1 = 0481900001: USB On-The-Go (OTG) Mini-B Receptacle, Right Angle, SMT, 0.80mm (.031") Pitch, Solder Tabs with Back Cover, Recessed Type; PCB_Layout: Complies with Manufacturer's Recommendation.
J2 J3 = Phonejack Stereo SW: 3-Conductor Jack with 2 break contacts (normals) and 2 auxiliary make contacts
L1-L9 = Inductor: Code_IEC: 1005
LS1 = Buzzer: Magnetic Transducer Buzzer
LS2 = Speaker: Loudspeaker
MK1 MK2 = Mic2: Microphone
P1 = Header 3X2A: Header, 3-Pin, Dual row
P2 = COAX-M: RF Coaxial PCB Connector, MMCX; Thru-Hole, Vertical Mount Plug,  50 Ohm Impedance; PackageDocument: Rev. A, 16-Jun-1997; PCB_Layout: Complies with manufacturer's recommendation.; DrillSize: Corresponds to nominal value.
Q1 = BC817-25: NPN General-purpose Transistor
Q2-Q7 = MOSFET-P: P-Channel MOSFET
Q8 = BC847: NPN General-purpose Transistor
R1-R60 = Res2: Resistor
S1-S3 = Key_u
U2 = 2_8LCD: 2.8"LCD SPI (ILI9341)
U3 = ATmega2560V-8AU: 8 MHz 8-bit AVR Microcontroller with 256KB Flash, 100-Pin TQFP Pkg, 86 I/Os, 12 PWMs, 4 USARTs, 16 ADC Channels, Industrial Temp
U4 = SN74LVC1T45: Преобразователь уровней
U5 = ADS7846E/2K5: 4-Wire Touch Screen Controller, 16-Pin SSOP
U13 U22 = MCP1700T-1202E/TT: Low Quiescent Current LDO, 3-Pin SOT-23, Extended Temperature, Tape and Reel
U15 = TEA5767
U17 U20 U21 = ncp698sq30T1
U18 = KXO-V97 генератор: Generator
U23 = micro_SD
U25 = DS1339U-3: I2C Serial Real-Time Clock (RTC), 3.0V, 8-Pin uMax/uSOP
VD1 = RGB_Led
Y1 Y3 Y4 = XTAL: Crystal Oscillator
Y2 = ECS-240-20-1: Crystal Oscillator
